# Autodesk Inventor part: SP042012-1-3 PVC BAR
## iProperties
Created: 2012-04
Part Number: SP042012-1-3 PVC BAR
Material: PVC-U
Document SubType Name: Modeling
Designer: Administrator
Density: 1.4 g/cm^3
Mass: 53.9852 g
Surface Area: 243.536 cm^2
Volume: 38.5608 cm^3
Author: Administrator
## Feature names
1. Extrusion1
